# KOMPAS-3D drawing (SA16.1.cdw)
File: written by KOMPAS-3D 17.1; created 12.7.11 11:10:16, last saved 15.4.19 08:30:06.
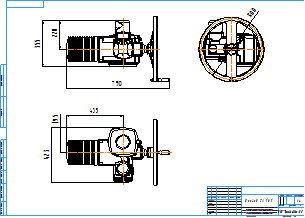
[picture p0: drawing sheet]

Title block, sheet 1: name: Привод SA 16.1; material: Внимание! Данный продукт является объектом авторского права ООО «Торговый Дом АДЛ». / Запрещается изменение, копирование, распространение / (в том числе путем копирования на другие сайты и ресурсы в Интернете) / или любое иное использование информации и объектов без предварительного / согласия правообладателя (ООО «Торговый Дом АДЛ»).; scale: 1:4; sheets: 1; organisation: ООО "Торговый дом АДЛ"; sheet format: A2; stored path: \\adlc.lan\data\АДЛ_ПКД\3D-модели\Поставщики\Сервоприводы AUMA\Электроприводы серии SA\KOMPAS 2D\Привод SA 16.1.cdw

Views: Проекционный вид 2, Проекционный вид 4, Проекционный вид 6
Dimensions and other numbers on the sheet: 435; 195; 423; 500; 790; 220; 355; 1:4; 1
